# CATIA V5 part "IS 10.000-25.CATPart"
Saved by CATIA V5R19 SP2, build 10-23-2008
Part number: IS 10.000-25
Bounding box of the stored display mesh (mm): x -97.324 to 97.324, y -97.5 to 97.5, z 0 to 210
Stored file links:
  C:\Users\Bora\Desktop\3D Katı model\IS serisi\IS 10.000\IS 10.000-25.CATPart
  C:\Program Files\Dassault Systemes\B19\intel_a\reffiles\standard\MetricThickPitch.txt
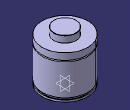
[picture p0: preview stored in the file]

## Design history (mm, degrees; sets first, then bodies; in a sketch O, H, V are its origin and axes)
Body1 (main body)
  Sketch1 on yz-plane, origin (0, 0, 0), H (0, 1, 0), V (0, 0, 1)
    point P2 (97.5, 154)
    line L1 (97.5, 154) -> (97.5, 182)
    point P3 (97.5, 149)
    line L2 (97.5, 16) -> (97.5, 149)
    line L3 (93.5, 16) -> (93.5, 8)
    point P8 (47.5, 209)
    arc A1 centre (46.5, 209) radius 1 from (47.5, 209) to (46.5, 210) ccw
    point P10 (47.5, 209)
    line L4 (47.5, 209) -> (47.5, 182)
    line L5 (97.5, 0) -> (97.5, 8)
    point P13 (97.5, 149)
    point P14 (97.5, 154)
    arc A2 centre (97.5, 151.5) radius 2.5 from (97.5, 154) to (97.5, 149) ccw
    line L6 (46.5, 210) -> (0, 210)
    line L7 (47.5, 182) -> (97.5, 182)
    line L8 (97.5, 0) -> (0, 0)
    line L9 (93.5, 16) -> (97.5, 16)
    line L10 (93.5, 8) -> (97.5, 8)
    tangency: L6 A1
    horizontal: L7 H, L8 H, L9 H, L10 H
    coincidence: P2 P14, P3 P13, P8 P10
  Shaft1: profile Sketch1, axis Sketch1.V, angle 360
  Sketch2 on face of Shaft1 from Sketch1.L8, origin (0, 0, 0), H (1, 0, 0), V (0, -1, 0)
    point P1 (60, 0)
    distance P1 V = 60
  Hole1: placed by Sketch2, at (60, 0, 0) direction (0, 0, 1), diameter 10.106, depth 12, threaded "M12", thread diameter 12, thread depth 12, pitch 1.75
  CircPattern1: of Hole1, instances 4, angular step 90, axis from xy-plane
